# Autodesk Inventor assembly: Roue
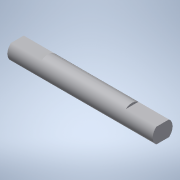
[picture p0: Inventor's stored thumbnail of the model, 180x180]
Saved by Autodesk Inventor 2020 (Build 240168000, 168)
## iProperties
Created: 2018-03
Part Number: Roue
Material: Générique
Document SubType Name: Assembly
Designer: Bruno
Author: Bruno
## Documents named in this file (2)
- C:\Users\bruno\Documents\1-Cours-2021-22\Maquettes-Inventor\Maquettes-Inventor-projets\Robot-2nde-Inventor\Roue.iam
- C:\Users\bruno\Documents\1-Cours-2021-22\Maquettes-Inventor\Maquettes-Inventor-projets\Robot-2nde-Inventor\Axe-moteur.ipt
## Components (1 placed, 1 different names)
1. Axe-moteur:1
